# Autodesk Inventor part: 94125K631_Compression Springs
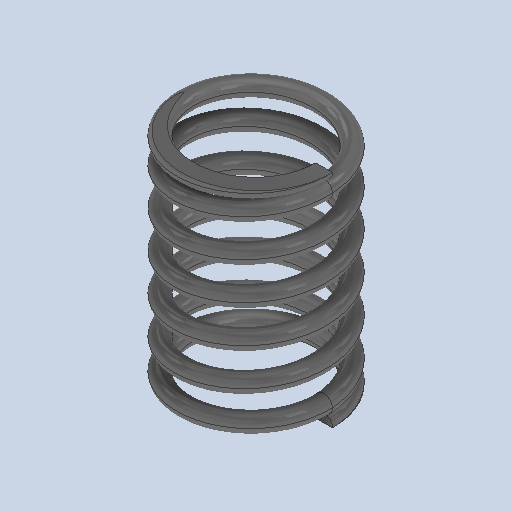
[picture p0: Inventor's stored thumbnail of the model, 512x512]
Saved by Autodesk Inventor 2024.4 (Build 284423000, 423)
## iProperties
Created: 2025-06
Part Number: 94125K631_Compression Springs
Material: Generic
Document SubType Name: Modeling
Designer: AdminForWorker
Density: 1 g/cm^3
Appearance: Default
Title: 94125K631_Compression Springs
Author: AdminForWorker
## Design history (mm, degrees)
feature "Body1"
body "Solid1"
